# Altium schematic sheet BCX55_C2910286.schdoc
size 127 x 101 mm
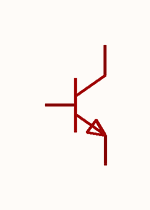
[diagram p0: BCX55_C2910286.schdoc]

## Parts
Q?  bcx55  [SOT-89-3L_L4.5-W2.5-P1.50-LS4.1-BR]  (value not drawn)

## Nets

Not connected (* = marked no-connect by the designer): Q? 1(B) 2(C) 3(E)

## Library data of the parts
Q? = bcx55: 晶体管类型:NPN;集电极电流(Ic):1A;集射极击穿电压(Vceo):60V;耗散功率(Pd):500mW;直流电流增益(hFE):63;; Manufacturer: CJ(江苏长电/长晶); Symbol: BCX55_C2910286; AddInBom: yes; ModelId: fb691090912a49e3bd79f7e2a6bd732b; ModelTransform: 157.48,177.165,0,0,0,0,-23.622,0,0; type: NPN; Current - Collector(Ic): 1A; Collector - Emitter Voltage VCEO: 60V; Pd - Power Dissipation: 500mW; DC Current Gain: 63; Transition frequency(fT): 130MHz; Current - Collector Cutoff: 100nA; Vce Saturation(VCE(sat)): 500mV; Emitter-Base Voltage(Vebo): 5V; Number: 1个NPN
